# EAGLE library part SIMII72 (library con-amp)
AMP connector
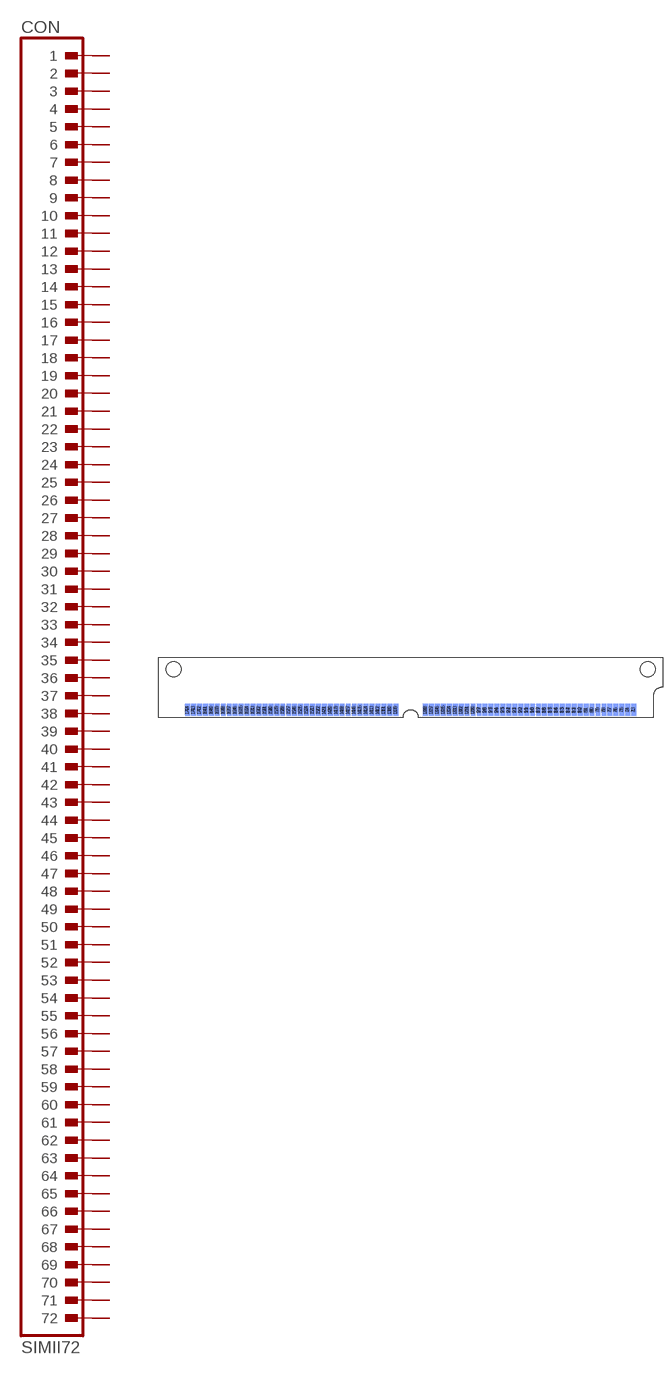
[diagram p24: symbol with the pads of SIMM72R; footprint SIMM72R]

Designator prefix CON

## SIMII72 (OC_FARNELL: unknown; OC_NEWARK: unknown)  [SIMM72R]
1  1  pas
2  2  pas
3  3  pas
4  4  pas
5  5  pas
6  6  pas
7  7  pas
8  8  pas
9  9  pas
10  10  pas
11  11  pas
12  12  pas
13  13  pas
14  14  pas
15  15  pas
16  16  pas
17  17  pas
18  18  pas
19  19  pas
20  20  pas
21  21  pas
22  22  pas
23  23  pas
24  24  pas
25  25  pas
26  26  pas
27  27  pas
28  28  pas
29  29  pas
30  30  pas
31  31  pas
32  32  pas
33  33  pas
34  34  pas
35  35  pas
36  36  pas
37  37  pas
38  38  pas
39  39  pas
40  40  pas
41  41  pas
42  42  pas
43  43  pas
44  44  pas
45  45  pas
46  46  pas
47  47  pas
48  48  pas
49  49  pas
50  50  pas
51  51  pas
52  52  pas
53  53  pas
54  54  pas
55  55  pas
56  56  pas
57  57  pas
58  58  pas
59  59  pas
60  60  pas
61  61  pas
62  62  pas
63  63  pas
64  64  pas
65  65  pas
66  66  pas
67  67  pas
68  68  pas
69  69  pas
70  70  pas
71  71  pas
72  72  pas
73  73  pas
74  74  pas
75  75  pas
76  76  pas
77  77  pas
78  78  pas
79  79  pas
80  80  pas
81  81  pas
82  82  pas
83  83  pas
84  84  pas
85  85  pas
86  86  pas
87  87  pas
88  88  pas
89  89  pas
90  90  pas
91  91  pas
92  92  pas
93  93  pas
94  94  pas
95  95  pas
96  96  pas
97  97  pas
98  98  pas
99  99  pas
100  100  pas
101  101  pas
102  102  pas
103  103  pas
104  104  pas
105  105  pas
106  106  pas
107  107  pas
108  108  pas
109  109  pas
110  110  pas
111  111  pas
112  112  pas
113  113  pas
114  114  pas
115  115  pas
116  116  pas
117  117  pas
118  118  pas
119  119  pas
120  120  pas
121  121  pas
122  122  pas
123  123  pas
124  124  pas
125  125  pas
126  126  pas
127  127  pas
128  128  pas
129  129  pas
130  130  pas
131  131  pas
132  132  pas
133  133  pas
134  134  pas
135  135  pas
136  136  pas
137  137  pas
138  138  pas
139  139  pas
140  140  pas
141  141  pas
142  142  pas
143  143  pas
144  144  pas

## Footprint SIMM72R (pad centres in mm)
SIMM II 72 Right Polarization
smd 1.041 x 2.54: 1 47.625,-8.636; 2 46.355,-8.636; 3 45.085,-8.636; 4 43.815,-8.636; 5 42.545,-8.636; 6 41.275,-8.636; 7 40.005,-8.636; 8 38.735,-8.636; 9 37.465,-8.636; 10 36.195,-8.636; 11 34.925,-8.636; 12 33.655,-8.636; 13 32.385,-8.636; 14 31.115,-8.636; 15 29.845,-8.636; 16 28.575,-8.636; 17 27.305,-8.636; 18 26.035,-8.636; 19 24.765,-8.636; 20 23.495,-8.636; 21 22.225,-8.636; 22 20.955,-8.636; 23 19.685,-8.636; 24 18.415,-8.636; 25 17.145,-8.636; 26 15.875,-8.636; 27 14.605,-8.636; 28 13.335,-8.636; 29 12.065,-8.636; 30 10.795,-8.636; 31 9.525,-8.636; 32 8.255,-8.636; 33 6.985,-8.636; 34 5.715,-8.636; 35 4.445,-8.636; 36 3.175,-8.636; 37 -3.175,-8.636; 38 -4.445,-8.636; 39 -5.715,-8.636; 40 -6.985,-8.636; 41 -8.255,-8.636; 42 -9.525,-8.636; 43 -10.795,-8.636; 44 -12.065,-8.636; 45 -13.335,-8.636; 46 -14.605,-8.636; 47 -15.875,-8.636; 48 -17.145,-8.636; 49 -18.415,-8.636; 50 -19.685,-8.636; 51 -20.955,-8.636; 52 -22.225,-8.636; 53 -23.495,-8.636; 54 -24.765,-8.636; 55 -26.035,-8.636; 56 -27.305,-8.636; 57 -28.575,-8.636; 58 -29.845,-8.636; 59 -31.115,-8.636; 60 -32.385,-8.636; 61 -33.655,-8.636; 62 -34.925,-8.636; 63 -36.195,-8.636; 64 -37.465,-8.636; 65 -38.735,-8.636; 66 -40.005,-8.636; 67 -41.275,-8.636; 68 -42.545,-8.636; 69 -43.815,-8.636; 70 -45.085,-8.636; 71 -46.355,-8.636; 72 -47.625,-8.636
smd 1.041 x 2.54 bottom: 73 47.625,-8.636; 74 46.355,-8.636; 75 45.085,-8.636; 76 43.815,-8.636; 77 42.545,-8.636; 78 41.275,-8.636; 79 40.005,-8.636; 80 38.735,-8.636; 81 37.465,-8.636; 82 36.195,-8.636; 83 34.925,-8.636; 84 33.655,-8.636; 85 32.385,-8.636; 86 31.115,-8.636; 87 29.845,-8.636; 88 28.575,-8.636; 89 27.305,-8.636; 90 26.035,-8.636; 91 24.765,-8.636; 92 23.495,-8.636; 93 22.225,-8.636; 94 20.955,-8.636; 95 19.685,-8.636; 96 18.415,-8.636; 97 17.145,-8.636; 98 15.875,-8.636; 99 14.605,-8.636; 100 13.335,-8.636; 101 12.065,-8.636; 102 10.795,-8.636; 103 9.525,-8.636; 104 8.255,-8.636; 105 6.985,-8.636; 106 5.715,-8.636; 107 4.445,-8.636; 108 3.175,-8.636; 109 -3.175,-8.636; 110 -4.445,-8.636; 111 -5.715,-8.636; 112 -6.985,-8.636; 113 -8.255,-8.636; 114 -9.525,-8.636; 115 -10.795,-8.636; 116 -12.065,-8.636; 117 -13.335,-8.636; 118 -14.605,-8.636; 119 -15.875,-8.636; 120 -17.145,-8.636; 121 -18.415,-8.636; 122 -19.685,-8.636; 123 -20.955,-8.636; 124 -22.225,-8.636; 125 -23.495,-8.636; 126 -24.765,-8.636; 127 -26.035,-8.636; 128 -27.305,-8.636; 129 -28.575,-8.636; 130 -29.845,-8.636; 131 -31.115,-8.636; 132 -32.385,-8.636; 133 -33.655,-8.636; 134 -34.925,-8.636; 135 -36.195,-8.636; 136 -37.465,-8.636; 137 -38.735,-8.636; 138 -40.005,-8.636; 139 -41.275,-8.636; 140 -42.545,-8.636; 141 -43.815,-8.636; 142 -45.085,-8.636; 143 -46.355,-8.636; 144 -47.625,-8.636
hole 3.175 at -50.597,0
hole 3.175 at 50.597,0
